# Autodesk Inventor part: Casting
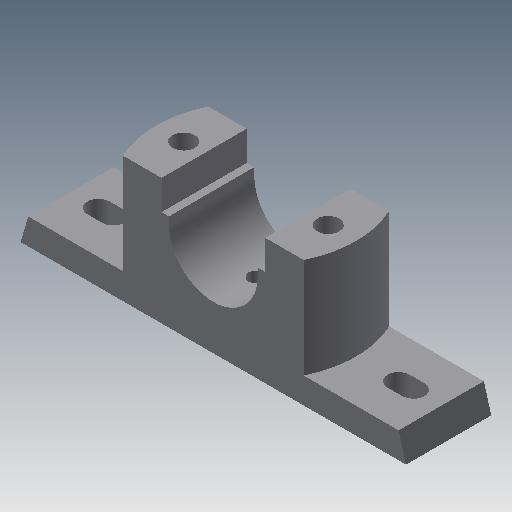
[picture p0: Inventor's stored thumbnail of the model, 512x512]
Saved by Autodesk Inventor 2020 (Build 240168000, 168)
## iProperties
Created: 2009-04
Part Number: Casting
Document SubType Name: Modeling
Designer: Sham
Density: 1 g/cm^3
Material: Generic
Appearance: Default
Author: Sham
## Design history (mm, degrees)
sketch "Sketch1"
  geometry: L1 (-104, 0)-(104, 0); L2 (-104, 0)-(-100, 14); L3 (-100, 14)-(100, 14); L4 (100, 14)-(104, 0); 1 further point
  constraints: 8 end point, 1 horizontal, 1 midpoint, 1 parallel, 1 other
  dimensions: "d0" = 208 distance of L1.start L1.end; "d1" = 104 distance of L1.end point (0, 0); "d2" = 4 horizontal distance of L1.start L2.end; "d3" = 4 horizontal distance of L1.end L3.end; "d10" = 14 distance between parallel lines of L1 L3
extrude "Extrusion1" new body sketch "Sketch1" stored distance "d4" = 46; taper "d5" = 0 deg
sketch "Sketch2"
  geometry: L1 (51.143, 46)-(148.857, 46); L2 (148.857, 0)-(51.143, 0); A1 r 54 centre (100, 23) between (51.143, 46) and (51.143, 0); A2 r 54 centre (100, 23) between (148.857, 0) and (148.857, 46)
  constraints: 4 end point, 4 point on circle, 2 centre point, 1 parallel
extrude "Extrusion2" join sketch "Sketch2" distance "d8" = 54; taper "d9" = 0 deg
sketch "Sketch3"
  geometry: L1 (-28, 68)-(-28, 52); L2 (-28, 52)-(-24, 52); L3 (28, 68)-(28, 52); L4 (28, 52)-(24, 52); L5 (-28, 68)-(28, 68); L6 (-100, 14)-(-48.857, 14) reference; L7 (0, 48)-(0, 19); L8 (48.857, 14)-(100, 14) reference; L9 (48.857, 68)-(-48.857, 68) reference; L10 (-24, 48)-(-24, 52); L11 (24, 48)-(24, 52); A1 r 24 centre (0, 48) between (-24, 48) and (24, 48); 1 further point
  constraints: 16 end point, 5 perpendicular, 2 point on circle, 2 symmetric about line, 1 centre point, 1 tangent, 1 vertical alignment, 1 other
  dimensions: "d11" = 16 distance of L1.start L1.end; "d16" = 24 radius of A1; "d17" = 16 distance of L3.start L3.end; "d52" = 56 distance between parallel lines of L1 L3; "d54" = 54 distance between parallel lines of L8 L9 (derived)
extrude "Extrusion3" cut sketch "Sketch3" distance "d18" = 54; taper "d19" = 0 deg
sketch "Sketch4"
  geometry: L1 (-23, 29)-(-15, 29); L2 (-15, 17)-(-23, 17); L3 (-185, 29)-(-177, 29); L4 (-177, 17)-(-185, 17); A1 r 6 centre (-15, 23) between (-15, 17) and (-15, 29); A2 r 6 centre (-23, 23) between (-23, 29) and (-23, 17); A3 r 6 centre (-177, 23) between (-177, 17) and (-177, 29); A4 r 6 centre (-185, 23) between (-185, 29) and (-185, 17)
  constraints: 8 end point, 8 point on circle, 8 tangent, 4 centre point, 3 parallel
  dimensions: "d20" = 8 distance of A1.centre A2.centre; "d21" = 6 radius of A1; "d24" = 6 radius of A3; "d25" = 8 distance of A4.centre A3.centre
extrude "Extrusion4" cut sketch "Sketch4" distance "d28" = 54; taper "d29" = 0 deg
sketch "Sketch5"
  geometry: L1 (208, 0)-(0, 0) reference; L2 (52, -10)-(78, -10); L3 (78, -10)-(78, -36); L4 (78, -36)-(52, -36); L5 (52, -36)-(52, -10); L6 (130, -10)-(156, -10); L7 (156, -10)-(156, -36); L8 (156, -36)-(130, -36); L9 (130, -36)-(130, -10); L10 (0, -46)-(208, -46) reference; L11 (104, -23)-(104, -46)
  constraints: 18 end point, 5 perpendicular, 4 parallel, 2 horizontal, 1 midpoint
  dimensions: "d30" = 26 distance of L2.start L2.end; "d31" = 10 distance between parallel lines of L2 L1; "d32" = 10 distance between parallel lines of L1 L6; "d65" = 26 distance between parallel lines of L3 L11; "d66" = 26 distance between parallel lines of L9 L11
extrude "Extrusion5" cut sketch "Sketch5" distance "d34" = 10; taper "d35" = 0 deg
sketch "Sketch6"
  geometry: L1 (148.857, 0)-(128, 0) reference; L2 (72, 0)-(51.143, 0) reference; L3 (0, 46)-(0, 0) reference; L4 (200, 46)-(200, 0) reference; C1 r 6 at (61, 23); C2 r 6 at (139, 23); 1 further point
  constraints: 2 centre point, 1 equal radius
  dimensions: "d36" = 12 diameter of C1; "d37" = 78 distance of C2.centre C1.centre; "d39" = 39 distance of C2.centre point (100, 23); "d58" = 39 distance of C1.centre point (100, 23); "d59" = 23 distance from line of L1 C2.centre; "d60" = 23 distance from line of L2 C1.centre; "d61" = 61 distance from line of L3 C1.centre; "d62" = 61 distance from line of L4 C2.centre (derived)
extrude "Extrusion6" cut sketch "Sketch6" extent not by distance; stored distance "d40" = 10; taper "d41" = 0 deg
workplane "Work Plane1"
sketch "Sketch7"
  geometry: L1 (-4, 46)-(204, 46) reference; L2 (-4, 0)-(-4, 46) reference; 1 further point
  dimensions: "d43" = 23 distance from line of L1 point (100, 23); "d44" = 104 distance from line of point (100, 23) L2
hole "Hole1" sketch "Sketch7" at (100, 23) diameter "d45" = 8; stored, may be unused: countersink angle "d49" = 90 deg, drill point angle "d51" = 118 deg; dims "d46" = 6, "d47" = 8, "d48" = 16, "d50" = 8
body "Solid1"
other parameters: "d6" = 108, "d42" = -52
